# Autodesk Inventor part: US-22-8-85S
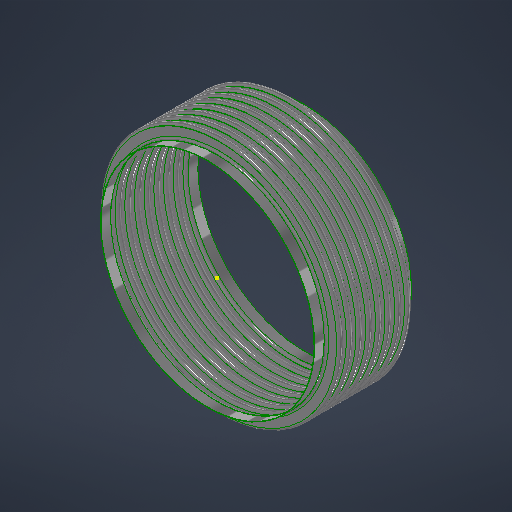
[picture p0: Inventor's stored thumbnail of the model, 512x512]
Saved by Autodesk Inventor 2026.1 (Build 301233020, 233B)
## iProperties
Category: 18 GA (0.048 THICK)
RuleStatus: InUse
Created: 2026-07
Part Number: US-22-8-85S
Project: =STOCK BELLOWS: <Stock Number><SFILL>
Material: ASTM A240-304
Description: =STOCK BELLOWS: <Stock Number>, <SID_> I.D., <SOD_> O.D., <SPLY_> PLY, <Category>, <SNET_CONS> CONS.<PITCH_><STANGENT_> TANGENT<SFILL>
Document SubType Name: Sheet Metal
Designer: LC
Stock Number: U.S-22-8-85S
Surface Area: 659.127 cm^2
Volume: 56.61 cm^3
Sheet Metal Rule: Default
Appearance: STAINLESS STEEL
NET_TUBE: 3.428
COUNTER: 1.500
PBAR: 1.214
PSET: 5.356
PLY: 2
CONS: 2
THK: 0.036
ID: 4.500
OD: 5.500
CONS_: 2
TANGENT: 0.500
PITCH: 0.375
BELLOWS_UPSET: 0.000
NET_CONS: 2
S_CONS: 0
Description_Units: 0
ID_M: 114.30 mm
OD_M: 139.70 mm
THK_M: 0.91 mm
ID_U: 4.500 in
OD_U: 5.500 in
THK_U: 0.036 in
TANGENT2: 0.500
d79: 1.000
d82: 1.000
d83: 26.000
d84: 24.000
d80: 2.571
d81: 10
SID: 2.375
SCONS_: 8
SPITCH: 0.250
SBELLOWS_UPSET: 0.000
SNET_CONS: 8
SS_CONS: 0
SCONS: 8
d174: 8
d177: 0.018
d178: 2.375
d179: 3.000
d180: 0.375
d181: 1.000
d182: 0.000
d190: 8
d191: 1
d192: 1
d193: 8
d194: 0
PART_NUMBER: U.S-22-8-85S
PRESSURE: 85
SIZE: 22.00
STANGENT_: 1.000
d214: 8
d217: 0.030
d218: 6.625
d219: 8.125
d220: 0.500
d221: 1.000
d222: 0.000
d230: 8
d231: 1
d232: 1
d233: 8
d234: 0
STANGENT: 4.000
SPLY_: 1
STHK_: 0.048
SID_: 22.000
SOD_: 24.750
SPITCH_: 1.000
STANGENT__: 1.000
SBELLOWS_UPSET_: 0.000
SDIFF_TAN: 1.000
TAN_TO_TAN: 0.750 in
d252: 2
d275: 2
d287: 0.050
d289: 0.500
d290: 0.000
d263: 2
d265: 1
d268: 2
d269: 0
d286: 2
d288: 1
d291: 2
d292: 0
SOD_NECK: 22 1/8
CFILL: .
SFILL: .
PITCH_: =, <SPITCH_> PITCH,
SREROLL: 0.750
MATTABLE: 20 GA (0.036 THICK)
MESH: ,
CSECT: 2
Author: LC
Keywords: 20 GA (0.036 THICK)
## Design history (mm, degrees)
sketch "Sketch2"
  geometry: L1 (0, -183.595)-(0, 600.956) reference; L2 (58.979, 0)-(57.15, 0); L3 (60.446, -1.467)-(66.554, -1.467); L4 (60.446, -3.296)-(66.554, -3.296); L5 (66.554, -8.058)-(60.446, -8.058); L6 (66.554, -6.229)-(60.446, -6.229); L7 (58.979, -9.525)-(57.15, -9.525); L8 (60.446, 0)-(60.446, -9.525); L9 (66.554, -4.762)-(69.85, -4.763); L10 (57.15, 0)-(57.15, -9.525); L11 (20.376, 102.841)-(20.376, 101.926); L12 (58.262, 488.877)-(58.262, 349.177); L13 (58.262, 479.352)-(58.262, 339.652); L14 (93.133, -58.817)-(93.133, -71.517); L15 (118.746, -66.401)-(118.746, -66.401); L16 (66.554, -6.229)-(66.554, -8.058); L17 (60.446, -6.229)-(60.446, -8.058); L18 (60.446, -7.144)-(66.554, -7.144); L19 (69.85, 0)-(69.85, -9.525); L20 (-66.554, -6.229)-(-66.554, -8.058); L21 (-66.554, -1.467)-(-60.446, -1.467); L22 (-66.554, -3.296)-(-60.446, -3.296); L23 (-60.446, -6.229)-(-66.554, -6.229); L24 (-66.554, -7.144)-(-60.446, -7.144); L25 (-60.446, -8.058)-(-66.554, -8.058); L26 (-60.446, -6.229)-(-60.446, -8.058); L27 (-57.15, -2.522)-(-57.15, -12.047); L28 (-60.446, -4.763)-(-57.15, -4.763); L29 (-66.554, 3.828)-(-66.554, -9.525); L30 (-68.021, 0)-(-69.85, 0); L31 (-69.85, 0)-(-69.85, -9.525); L32 (-68.021, -9.525)-(-69.85, -9.525); A1 r 1.467 centre (60.446, 0) between (58.979, 0) and (60.446, -1.467); A2 r 3.296 centre (60.446, 0) between (57.15, 0) and (60.446, -3.296); A3 r 3.296 centre (66.554, -4.762) between (66.554, -8.058) and (66.554, -1.467); A4 r 1.467 centre (66.554, -4.762) between (66.554, -6.229) and (66.554, -3.296); A5 r 1.467 centre (60.446, -9.525) between (60.446, -8.058) and (58.979, -9.525); A6 r 3.296 centre (60.446, -9.525) between (60.446, -6.229) and (57.15, -9.525); A7 r 2.381 centre (66.554, -4.762) between (66.554, -7.144) and (68.936, -4.762); A8 r 2.381 centre (60.446, -9.525) between (60.446, -7.144) and (58.064, -9.525); A9 r 1.467 centre (-66.554, -9.525) between (-66.554, -8.058) and (-68.021, -9.525); A10 r 1.467 centre (-60.446, -4.763) between (-60.446, -6.229) and (-60.446, -3.296); A11 r 2.381 centre (-60.446, -4.763) between (-60.446, -7.144) and (-58.064, -4.763); A12 r 3.296 centre (-60.446, -4.763) between (-60.446, -8.058) and (-60.446, -1.467); A13 r 2.381 centre (-66.554, -9.525) between (-66.554, -7.144) and (-68.936, -9.525); A14 r 3.296 centre (-66.554, -9.525) between (-66.554, -6.229) and (-69.85, -9.525); A15 r 1.467 centre (-66.554, 0) between (-68.021, 0) and (-66.554, -1.467); A16 r 3.296 centre (-66.554, 0) between (-69.85, 0) and (-66.554, -3.296); 10 further points
  constraints: 62 end point, 38 point on circle, 20 tangent, 16 centre point, 12 parallel, 9 midpoint, 7 vertical, 6 coincident, 6 concentric, 6 point on line, 4 equal radius, 4 perpendicular, 3 horizontal, 1 collinear, 1 horizontal alignment, 10 other
  dimensions: "THK" = 0.9144 distance of L11.start L11.end; "ID" = 114.3 distance of L11.end point (20.376, -12.374); "OD" = 139.7 distance of L12.start L12.end; "PITCH" = 9.525 distance of L12.start L13.start; "TANGENT" = 12.7 distance of L14.start L14.end; "BELLOWS_UPSET" = 0 distance of L15.start L15.end; "d43" = 114.3 diameter of L10 L1 (= ID); "d44" = 139.7 diameter of L9.end L1 (= OD); "d45" = 1.8288 distance between parallel lines of L5 L6 (computed from THK, PLY); "d46" = 3.29565 radius of A3 (computed from PITCH, THK, PLY); "UPSET_PITCH" = 9.525 distance of L2.end L7.end (derived); "SIDEWALL_ANGLE" = 0 deg angle of L3 L9 (derived); "CON_GAP" = 2.9337 distance of point (60.446, -6.229) point (60.446, -3.296) (derived); "TAN1" = 3.74046 dimension on A8 (derived); "TAN2" = 3.74046 dimension on A7 (derived); "LEG1" = 6.1087 distance of L18.start L18.end (derived); "d278" = 1.8288 distance between parallel lines of L25 L23 (derived); "d279" = 3.29565 radius of A12 (derived); "d280" = 9.525 distance of L30.end L31.end (derived); "d281" = 360 deg dimension on L21 L28 (derived); "d282" = 2.9337 distance of point (-66.554, -6.229) point (-66.554, -3.296) (derived); "d283" = 3.74046 dimension on A13 (derived); "d284" = 3.74046 dimension on A11 (derived); "d285" = 6.1087 distance of L24.start L24.end (derived); "d293" = 114.3 diameter of L27 L1 (derived); "d294" = 139.7 diameter of L31 L1 (derived)
  node "Sketch Rectangular Pattern1" dims "d31" = 25.4, "ID" = 114.3
  node "Sketch Rectangular Pattern2" dims "d39" = 25.4, "PITCH" = 9.525
revolve "CONS" stored, may be unused: angle "d48" = 90 deg
node "BELLOW MIDPLANE"
pattern_linear "Rectangular Pattern2" dims "d52" = 9.525 (= UPSET_PITCH)
sketch "Sketch5"
  geometry: C1 r 58.979 at (0, 0) reference; C2 r 57.15 at (0, 0) reference
extrude "TANGENT" new body sketch "Sketch5" distance "d53" = 12.7 (= TANGENT); taper "d54" = 0 deg
revolve "SAMETAN" stored, may be unused: angle "d65" = 90 deg
revolve "DIFFTAN" stored, may be unused: angle "d70" = 90 deg
sketch "Sketch9"
  geometry: L1 (58.391, 0)-(-58.391, 0) reference; L2 (0, -17.78)-(0, 17.78) reference; L3 (41.708, 0)-(-41.708, 0); L4 (41.708, -11.906)-(41.708, 11.906); L5 (29.008, -11.906)-(29.008, 11.906); L6 (15.418, 11.906)-(15.418, -11.906); L7 (-29.008, -11.906)-(-29.008, 11.906); L8 (-41.708, -11.906)-(-41.708, 11.906); L9 (40.914, -11.906)-(40.914, 11.906); L10 (41.708, -11.906)-(40.914, -11.906); L11 (41.708, 11.906)-(40.914, 11.906); L12 (15.815, 11.906)-(15.022, 11.906); L13 (15.022, 11.906)-(15.022, -11.906); L14 (15.022, -11.906)-(15.815, -11.906); L15 (15.815, -11.906)-(15.815, 11.906); L16 (-15.815, 11.906)-(-15.815, -11.906); L17 (-15.418, 11.906)-(-15.418, -11.906); L18 (-15.815, -11.906)-(-15.022, -11.906); L19 (-15.022, -11.906)-(-15.022, 11.906); L20 (-15.022, 11.906)-(-15.815, 11.906); L21 (-41.708, -11.906)-(-40.914, -11.906); L22 (-40.914, -11.906)-(-40.914, 11.906); L23 (-40.914, 11.906)-(-41.708, 11.906); L24 (-41.708, 11.906)-(-41.708, -11.906); L25 (41.708, -0.397)-(-41.708, -0.397); L26 (-41.708, -0.397)-(-41.708, 0.397); L27 (-41.708, 0.397)-(41.708, 0.397); L28 (41.708, 0.397)-(41.708, -0.397); L29 (-41.708, 11.906)-(41.708, 11.906); L30 (41.708, 11.906)-(41.708, 12.7); L31 (41.708, 12.7)-(-41.708, 12.7); L32 (-41.708, 12.7)-(-41.708, 11.906); L33 (41.708, -11.906)-(-41.708, -11.906); L34 (-41.708, -11.906)-(-41.708, -12.7); L35 (-41.708, -12.7)-(41.708, -12.7); L36 (41.708, -12.7)-(41.708, -11.906); 30 further points
  constraints: 68 end point, 13 midpoint, 13 parallel, 8 horizontal, 7 perpendicular, 6 equal length, 3 point on line, 2 vertical, 14 other
  dimensions: "d115" = 23.8125 distance of L4.start L4.end (derived); "d116" = 12.7 distance between parallel lines of L4 L5 (derived); "d117" = 13.58962 distance between parallel lines of L5 L6 (derived); "d125" = 44.42645 distance between parallel lines of L7 L6 (derived); "d127" = 12.7 distance between parallel lines of L8 L7 (derived); "d128" = 26.28962 distance between parallel lines of L6 L4 (derived); "d130" = 83.41607 distance between parallel lines of L8 L4 (derived); "RULER_THK" = 0.79375 distance between parallel lines of L4 L9; "d135" = 0.79375 distance of L13.end L14.end (derived); "d138" = 30.83684 distance of L13.end L16.end (derived); "d143" = 0.79375 distance of L22.end L8.end (derived); "d144" = 0.79375 distance between parallel lines of L27 L25 (derived)
extrude "RULER" join sketch "Sketch9" distance "d149" = 0.79375 (derived); taper "d150" = 0 deg
extrude "BARS" join sketch "Sketch9" distance "d151" = 0.79375 (derived); taper "d152" = 0 deg
pattern_linear "Rectangular Pattern4" dims "d155" = 30.83684 (derived)
sketch "Sketch13"
  geometry: L1 (93.149, -52.467)-(93.149, -77.867); L2 (280.619, 0)-(279.4, 0); L3 (280.619, -25.4)-(279.4, -25.4); L4 (307.365, -19.66)-(286.36, -19.66); L5 (307.365, -18.44)-(286.36, -18.44); L6 (307.365, -12.7)-(314.325, -12.7); L7 (286.36, -5.74)-(307.365, -5.74); L8 (286.36, 0)-(286.36, -25.4); L9 (279.4, 0)-(279.4, -25.4); L10 (58.254, -184.223)-(58.254, -812.873); L11 (58.254, -209.623)-(58.254, -838.273); L12 (58.254, -260.423)-(58.254, -889.073); L13 (58.254, -285.823)-(58.254, -914.473); L14 (58.254, -311.223)-(58.254, -939.873); L15 (58.254, -336.623)-(58.254, -965.273); L16 (58.254, -362.023)-(58.254, -990.673); L17 (58.254, -235.023)-(58.254, -863.673); L18 (20.376, 103.145)-(20.376, 101.926); L19 (286.36, -6.96)-(307.365, -6.96); L20 (0, -1163.716)-(0, 314.289) reference; L21 (-57.15, 0)-(342.9, 0) reference; A1 r 5.74 centre (286.36, 0) between (280.619, 0) and (286.36, -5.74); A2 r 5.74 centre (286.36, -25.4) between (286.36, -19.66) and (280.619, -25.4); A3 r 6.96 centre (286.36, -25.4) between (286.36, -18.44) and (279.4, -25.4); A4 r 5.74 centre (307.365, -12.7) between (307.365, -18.44) and (307.365, -6.96); A5 r 6.96 centre (307.365, -12.7) between (307.365, -19.66) and (307.365, -5.74); A6 r 6.96 centre (286.36, 0) between (279.4, 0) and (286.36, -6.96); 6 further points; 1 other entity
  constraints: 38 end point, 15 point on circle, 9 tangent, 6 centre point, 6 parallel, 5 vertical alignment, 4 point on line, 4 vertical, 3 coincident, 3 concentric, 2 collinear, 2 equal radius, 1 horizontal, 1 perpendicular, 23 other
  dimensions: "SBELLOWS_UPSET_" = 0 distance of point (118.762, -66.401) point (118.762, -66.401); "STOTAL_THK_BELLOW__" = 1.2192 distance between parallel lines of L4 L5 (derived); "d224" = 6.9596 radius of A5 (derived); "d225" = 25.4 distance of L2.end L3.end (derived); "SSIDEWALL_ANGLE_" = 0 deg angle of L7 L6 (derived); "SSCON_GAP_" = 11.4808 distance of point (286.36, -18.44) point (286.36, -6.96) (derived); "d235" = 558.8 diameter of L9 L20 (derived); "d236" = 628.65 diameter of L6.end L20 (derived)
  node "Sketch Rectangular Pattern4" dims "d228" = 25.4
  node "Sketch Rectangular Pattern5" dims "d229" = 25.4
revolve "SBELLOW" stored, may be unused: angle "d197" = 90 deg
pattern_linear "Rectangular Pattern5" dims "d204" = 25.4 (derived)
revolve "STANGENT" stored, may be unused: angle "d240" = 90 deg
revolve "SSAMETAN" stored, may be unused: angle "d241" = 90 deg
revolve "SDIFFTAN" stored, may be unused: angle "d246" = 90 deg
revolve "INVCON" stored, may be unused: angle "d295" = 90 deg
pattern_linear "Rectangular Pattern6" dims "d298" = 9.525 (derived)
revolve "INVTANGENT" stored, may be unused: angle "d302" = 90 deg
revolve "INVSAMETAN" stored, may be unused: angle "d307" = 90 deg
revolve "INVDIFFTAN" stored, may be unused: angle "d312" = 90 deg
sketch "ID BELLOW MOUNT CALC"
  geometry: L1 (44.45, 0)-(38.1, 0); L2 (38.1, 0)-(38.1, 12.7); L3 (38.1, 12.7)-(44.45, 12.7); L4 (44.45, 12.7)-(44.45, 0); L5 (36.513, 12.7)-(34.684, 12.7); L6 (34.684, 12.7)-(34.684, 0); L7 (34.684, 0)-(36.513, 0); L8 (36.513, 0)-(36.513, 12.7); L9 (0, -2.54)-(0, 15.24) reference; L10 (-8.89, 0)-(53.34, 0) reference; 1 further point
  constraints: 16 end point, 5 parallel, 2 collinear, 2 horizontal, 2 perpendicular
  dimensions: "d314" = 12.7 distance of L5.end L6.end (derived); "d315" = 1.8288 distance of L5.start L5.end (derived); "IG" = 1.5875 distance between parallel lines of L2 L8; "PIPE_OD" = 88.9 diameter of L4 L9; "PIPE_WALL" = 6.35 distance of L2.end L3.end; "ID_MT_BELLOW" = 69.3674 diameter of L6 L9 (derived)
revolve "CFILL" stored, may be unused: angle "d320" = 90 deg
pattern_linear "Rectangular Pattern7" dims "d323" = 9.525 (derived)
revolve "SFILL" stored, may be unused: angle "d324" = 90 deg
pattern_linear "Rectangular Pattern8" dims "d327" = 25.4 (derived)
node "STOCK BELLOW MIDPLANE"
sketch "Sketch21"
  geometry: L1 (0, -100.013)-(0, 100.013) reference; L2 (-100.013, 0)-(100.013, 0) reference; L3 (-0.099, 71.437)-(0.099, 71.437); L4 (0.099, 71.437)-(0.099, 55.562); L5 (0.099, 55.562)-(-0.099, 55.562); L6 (-0.099, 55.562)-(-0.099, 71.437); C1 r 55.562 at (0, 0); C2 r 71.437 at (0, 0); 3 further points
  constraints: 8 end point, 2 centre point, 2 coincident, 2 parallel, 2 tangent, 1 horizontal, 1 perpendicular, 1 other
  dimensions: "d329" = 111.125 diameter of C1 (derived); "d330" = 142.875 diameter of C2 (derived); "d331" = 0.19844 distance of L3.start L3.end
extrude "CLAMSHELL" cut sketch "Sketch21" extent not by distance; stored distance "d332" = 0; taper "d333" = 0 deg
pattern_circular "Circular Pattern1" dims angle "d335" = 180 deg (derived)
node "BELLOW"
sketch "Sketch6"
  geometry: L1 (-19.05, 58.979)-(-6.35, 58.979); L2 (-6.35, 58.979)-(-6.35, 57.15); L3 (-6.35, 57.15)-(-19.05, 57.15); L4 (-19.05, 57.15)-(-19.05, 58.979); L5 (2.54, 0)-(-59.69, 0) reference; L6 (-38.1, -108.388)-(-38.1, 156.601) reference; 1 further point
  constraints: 8 end point, 2 parallel, 1 horizontal, 1 perpendicular
  dimensions: "d61" = 12.7 distance of L2.end L3.end (derived); "d62" = 1.8288 distance of L1.end L2.end (derived); "d63" = 114.3 diameter of L3 L5 (derived); "d64" = 19.05 distance between parallel lines of L4 L6 (derived)
sketch "Sketch12"
  geometry: 1 further point
sketch "Sketch14"
  geometry: L1 (-25.4, 280.619)-(0, 280.619); L2 (0, 280.619)-(0, 279.4); L3 (0, 279.4)-(-25.4, 279.4); L4 (-25.4, 279.4)-(-25.4, 280.619); L5 (5.08, 0)-(-30.48, 0) reference; L6 (0, -51.044)-(0, 306.263) reference; 1 further point
  constraints: 8 end point, 2 parallel, 1 collinear, 1 horizontal, 1 perpendicular
  dimensions: "d237" = 1.2192 distance of L3.end L1.start (derived); "d238" = 558.8 diameter of L3 L5 (derived); "d239" = 25.4 distance of L1.start L1.end (derived); "SOD_NECK" = 561.2384 diameter of L1 L5 (derived)
sketch "Sketch15"
  geometry: L1 (-51.044, 0)-(306.263, 0) reference; L2 (279.4, -203.2)-(280.619, -203.2); L3 (280.619, -203.2)-(280.619, -228.6); L4 (280.619, -228.6)-(279.4, -228.6); L5 (279.4, -228.6)-(279.4, -203.2); L6 (0, -276.86)-(0, 60.96) reference; 1 further point
  constraints: 8 end point, 2 parallel, 1 horizontal, 1 perpendicular
  dimensions: "d205" = 25.4 distance of L4.end L2.start (derived); "d206" = 1.2192 distance of L3.end L4.end (derived); "d207" = 558.8 diameter of L5 L6 (derived); "d208" = 203.2 distance between parallel lines of L1 L2 (derived)
node "TANGENT_"
node "SAME_TAN"
sketch "Sketch8"
  geometry: L1 (58.979, -19.05)-(57.15, -19.05); L2 (57.15, -19.05)-(57.15, -31.75); L3 (57.15, -31.75)-(58.979, -31.75); L4 (58.979, -31.75)-(58.979, -19.05); L5 (0, -40.64)-(0, 21.59) reference; L6 (-108.388, 0)-(156.601, 0) reference; 1 further point
  constraints: 8 end point, 2 parallel, 1 horizontal, 1 perpendicular
  dimensions: "d66" = 114.3 diameter of L2 L5 (derived); "TOTAL_THK_BELLOW" = 1.8288 distance of L2.end L3.end (derived); "d68" = 19.05 distance between parallel lines of L1 L6 (derived); "d69" = 12.7 distance of L1.end L2.end (derived)
node "DIFF_TAN"
node "Sketch Rectangular Pattern3" dims "d138" = 30.83684 (derived), "d141" = 25.4
node "SBELLOW_"
node "STANGENT_"
node "SSAME_TAN"
sketch "Sketch16"
  geometry: L1 (280.619, -203.2)-(279.4, -203.2); L2 (279.4, -203.2)-(279.4, -228.6); L3 (279.4, -228.6)-(280.619, -228.6); L4 (280.619, -228.6)-(280.619, -203.2); L5 (0, -276.86)-(0, 60.96) reference; L6 (-51.044, 0)-(306.263, 0) reference; 1 further point
  constraints: 8 end point, 2 parallel, 1 horizontal, 1 perpendicular
  dimensions: "SDIFF_TAN" = 25.4 distance of L3.end L1.start; "d243" = 1.2192 distance of L2.end L3.end (derived); "d244" = 203.2 distance between parallel lines of L1 L6 (derived); "d245" = 558.8 diameter of L2 L5 (derived)
node "SDIFF_TAN"
body "Solid15"
sketch "Sketch17"
  geometry: L1 (69.85, 12.7)-(68.021, 12.7); L2 (68.021, 12.7)-(68.021, 0); L3 (68.021, 0)-(69.85, 0); L4 (69.85, 0)-(69.85, 12.7); L5 (0, -2.54)-(0, 15.24) reference; L6 (-13.97, 0)-(83.82, 0) reference; 2 further points
  constraints: 8 end point, 2 parallel, 1 horizontal, 1 midpoint, 1 perpendicular, 1 point on line
  dimensions: "INVTANGENT" = 12.7 distance of L3.end L1.start (derived); "d300" = 1.8288 distance of L1.start L1.end (derived); "d301" = 139.7 diameter of L4 L5 (derived)
body "Solid16"
sketch "Sketch18"
  geometry: L1 (69.85, -19.05)-(68.021, -19.05); L2 (68.021, -19.05)-(68.021, -31.75); L3 (68.021, -31.75)-(69.85, -31.75); L4 (69.85, -31.75)-(69.85, -19.05); L5 (-13.97, 0)-(83.82, 0) reference; L6 (0, -40.64)-(0, 21.59) reference; 1 further point
  constraints: 8 end point, 2 parallel, 1 horizontal, 1 perpendicular
  dimensions: "d303" = 19.05 distance between parallel lines of L1 L5 (derived); "d304" = 12.7 distance of L3.end L1.start (derived); "d305" = 1.8288 distance of L2.end L3.end (derived); "d306" = 139.7 diameter of L4 L6 (derived)
body "Solid17"
sketch "Sketch19"
  geometry: L1 (69.85, -19.05)-(68.021, -19.05); L2 (68.021, -19.05)-(68.021, -31.75); L3 (68.021, -31.75)-(69.85, -31.75); L4 (69.85, -31.75)-(69.85, -19.05); L5 (0, -40.64)-(0, 21.59) reference; L6 (-13.97, 0)-(83.82, 0) reference; 1 further point
  constraints: 8 end point, 2 parallel, 1 horizontal, 1 perpendicular
  dimensions: "d308" = 12.7 distance of L1.end L2.end (derived); "d309" = 139.7 diameter of L4 L5 (derived); "d310" = 1.8288 distance of L2.end L3.end (derived); "d311" = 19.05 distance between parallel lines of L1 L6 (derived)
body "Solid18"
body "Solid19"
body "Solid20"
other parameters: "BMPL" = -101.6, "PSET" = 136.0424 (computed from OD, THK, PLY) [user parameter], "PBAR" = 30.83684 (= 0.570796 x PITCH + OD - ID) [user parameter; used in 1 equation term], "COUNTER" = 15 [user parameter], "NET_TUBE" = 87.07367 (computed from CONS_, PBAR, TANGENT) [user parameter], "S_CONS" = 0 [user parameter; used in 1 equation term], "ID_M" = 114.3 (= ID) [user parameter], "OD_M" = 139.7 (= OD) [user parameter], "THK_M" = 0.9144 (= THK) [user parameter], "ID_U" = 114.3 (= ID) [user parameter], "OD_U" = 139.7 (= OD) [user parameter], "THK_U" = 0.9144 (= THK) [user parameter], "D_UNITS" = 0 [user parameter], "TANGENT2" = 12.7 [user parameter], "TAN_TO_TAN" = 19.05 [user parameter], "OD_NECK" = 117.9576 [user parameter], "d79" = 25.4, "d80" = 65.29823 [user parameter], "d82" = 25.4, "d83" = 660.4, "d84" = 609.6, "sa_0" = 4, "FRAME_THK" = 0.79375 [user parameter], "CON_FLAT" = 13.58962 [user parameter], "SID" = 60.325 [user parameter], "SPITCH" = 6.35 [user parameter], "STANGENT_" = 25.4 [user parameter], "SBELLOWS_UPSET" = 0 [user parameter], "SS_CONS" = 0 [user parameter], "STAN_TO_TAN_" = 203.2 [user parameter], "d100" = 1.2192 [user parameter], "d191" = 25.4 [user parameter], "d194" = 0 [user parameter], "STANGENT" = 101.6 [user parameter], "d234" = 0 [user parameter], "SUPSET_PITCH_" = 25.4 [user parameter], "d269" = 0 [user parameter], "d287" = 1.27, "d289" = 12.7, "d290" = 0, "d292" = 0 [user parameter], "Thickness" = 3.048 (derived), "KFactor" = 4.4, "BendRadius" = 3.048 (derived), "BendReliefWidth" = 3.048 (derived), "BendReliefDepth" = 1.524 (derived), "CornerReliefSize" = 12.192 (derived), "SeamGap" = 0.00508, "MinimumRemnant" = 6.096 (derived), "TransitionRadius" = 3.048 (derived), "JacobiRadiusSize" = 3.048 (derived), "GapSize" = 3.048 (derived), "SREROLL" = 19.05 [user parameter], "CUR_STK_PITCH" = 25.4 [user parameter], "d328" = -101.6 (derived), "CSECTDEG" = 180 deg [user parameter]
